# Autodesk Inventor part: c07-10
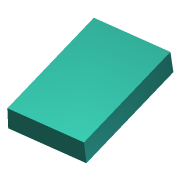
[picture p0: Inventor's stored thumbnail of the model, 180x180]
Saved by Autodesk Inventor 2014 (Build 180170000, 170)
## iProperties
Created: 2010-12
Part Number: c07-10
Material: Generic
Document SubType Name: Modeling
Designer: Beta-8540w
Density: 1 g/cm^3
Appearance: Smooth - Aqua
Author: Beta-8540w
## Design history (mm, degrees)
sketch "Sketch1"
  geometry: L1 (-25, 0)-(25, 0); L2 (25, 0)-(25, 80); L3 (25, 80)-(-25, 80); L4 (-25, 80)-(-25, 0); 2 further points
  constraints: 8 end point, 2 parallel, 1 coincident, 1 horizontal, 1 midpoint, 1 perpendicular
  dimensions: "d0" = 50 distance of L3.end L2.end; "d1" = 80 distance of L2.end L1.end
extrude "Extrusion1" new body sketch "Sketch1" distance "d2" = 15; taper "d3" = 0 deg
feature "FaceDraft1" dims angle "d4" = -2 deg
body "Solid1"
